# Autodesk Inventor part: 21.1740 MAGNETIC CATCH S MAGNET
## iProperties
Created: 2007-03
Part Number: 21.1740 MAGNETIC CATCH S MAGNET
Document SubType Name: Modeling
Designer: Andy Moles
Material: ABS Plastic
Density: 1.06 g/cm^3
Author: Andy Moles
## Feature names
1. Extrusion1
2. Revolution1
3. Extrusion2
4. Extrusion3
